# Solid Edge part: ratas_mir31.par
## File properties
Author: Kalle
Template: Iso Part.par
Last saved by: Kalle
Revision: 2
Application: Solid Edge
Accuracy: 0,990
Username: Kalle
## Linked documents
ratas_mir3.par
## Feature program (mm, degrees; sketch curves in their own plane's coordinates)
part copy "CopiedPart_1"
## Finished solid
Body 1: solid body, 6 faces, 6 edges, 0 vertices.
  Faces by surface: cylinder 3, plane 3
  Edges by curve: circle 6
Bounding box of the edges (mm): 30.000 x 12.000 x 30.000, from (13.8781, -12, -41.601) to (43.8781, 0, -11.601).
Cylindrical faces by radius (mm): R4 x1, R10 x1, R15 x1
Planar faces by outward normal: +y 1, -y 2
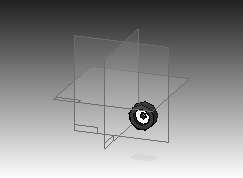
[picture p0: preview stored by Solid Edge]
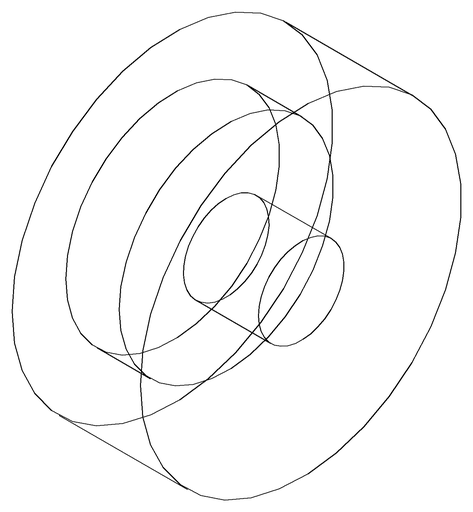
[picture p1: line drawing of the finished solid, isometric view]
